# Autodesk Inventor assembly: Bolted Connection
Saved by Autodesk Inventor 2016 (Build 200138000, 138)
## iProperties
Created: 2016-01
Part Number: Bolted Connection
Document SubType Name: Assembly
Designer: Black Falcon
ClientObjectVersion: 1
Author: Black Falcon
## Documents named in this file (2)
- E:\Learning Inventor\Belt Friction Apparatus\Final Assembly\Design Accelerator\Bolted Connection3.iam
- C:\Users\Black Falcon\Documents\Inventor\Content Center Files\R2016\en-US\ANSI ASME B18.2.1(2)\ANSI_ASME B18.2.1 - 5_16-18 UNC - 1.25(2).ipt
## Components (1 placed, 1 different names)
1. Hex Bolt - Inch 5/16-18 UNC - 1.25:1
